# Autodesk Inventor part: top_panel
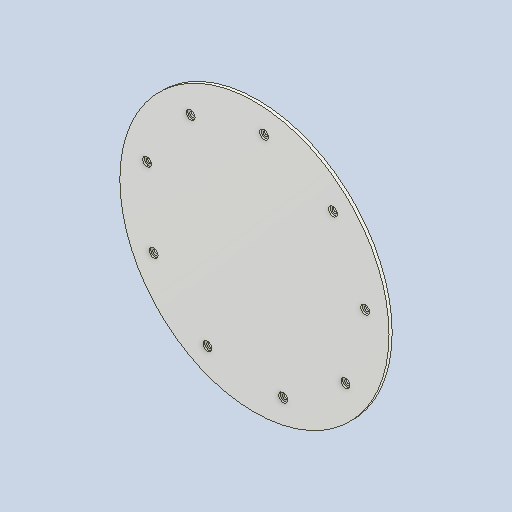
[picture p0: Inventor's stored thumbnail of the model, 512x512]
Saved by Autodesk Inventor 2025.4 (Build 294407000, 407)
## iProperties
Created: 2026-09
Part Number: top_panel
Material: Generic
Document SubType Name: Modeling
Designer: AdminForWorker
Density: 1 g/cm^3
Appearance: Default
Title: top_panel v5 v2
Author: AdminForWorker
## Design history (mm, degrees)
feature "Body1"
body "Solid1"
